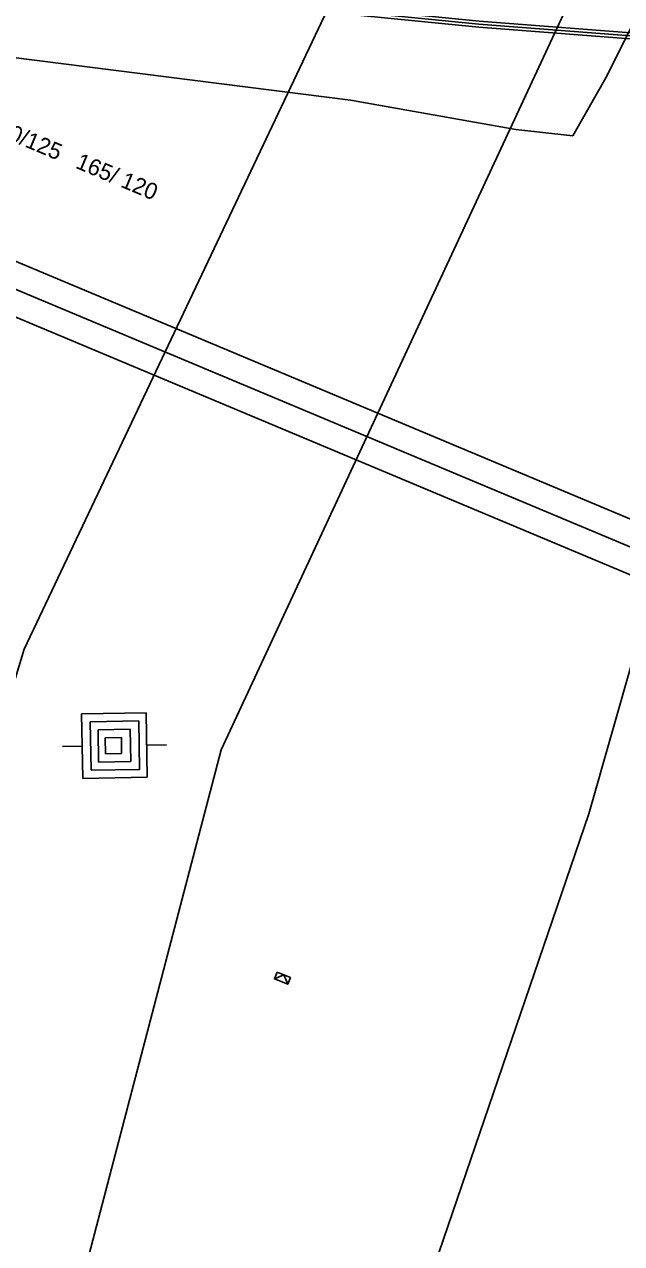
# Model space of a CAD drawing. Extents: x -596024 to -594475, y -1163820 to -1161957.
# Drawn here: x -594977.6 to -594948.5, y -1162194.5 to -1162135 of the extents above; entities that cross this region are included whole.
import ezdxf

# ---------------------------------------------------------------- set-up
doc = ezdxf.new("R2010")
doc.units = 0
for name, color, linetype in [('Vrstva 12', 7, 'Continuous'), ('Vrstva 19', 7, 'Continuous'), ('Vrstva 29', 7, 'Continuous'), ('Vrstva 30', 7, 'Continuous'), ('Vrstva 32', 7, 'Continuous'), ('Vrstva 42', 7, 'Continuous'), ('Vrstva 43', 7, 'Continuous'), ('Vrstva 47', 7, 'Continuous'), ('Vrstva 53', 7, 'Continuous')]:
    doc.layers.add(name, color=color, linetype=linetype)

# ---------------------------------------------------------------- blocks, each defined once
blk = doc.blocks.new('WN200')
at = {"layer": 'Vrstva 53'}
for points in [[(0, 6.3), (0, 10.136)], [(-6.299, 6.3), (6.299, 6.3)], [(-6.299, -6.3), (-6.299, 6.3)], [(6.299, 6.3), (6.299, -6.3)], [(-4.724, 4.625), (4.724, 4.625)], [(-4.724, -4.823), (-4.724, 4.625)], [(-3.149, 3.151), (3.149, 3.151)], [(-3.149, -3.151), (-3.149, 3.151)], [(3.149, 3.151), (3.149, -3.151)], [(4.724, 4.625), (4.724, -4.823)], [(-1.575, -1.378), (-1.575, 1.772)], [(-1.575, 1.772), (1.575, 1.772)], [(1.575, 1.772), (1.575, -1.378)], [(1.575, -1.378), (-1.575, -1.378)], [(3.149, -3.151), (-3.149, -3.151)], [(6.299, -6.3), (-6.299, -6.3)], [(4.724, -4.823), (-4.724, -4.823)], [(0, -6.3), (0, -10.136)]]:
    blk.add_lwpolyline(points, dxfattribs=at)

msp = doc.modelspace()

# ---------------------------------------------------------------- linework, layer by layer
at = {"layer": 'Vrstva 12'}
msp.add_lwpolyline([(-594938.65, -1162132.45), (-594939.94, -1162137.9), (-594940.48, -1162142.29), (-594945.83, -1162158.49), (-594946.79, -1162162.06), (-594950.07, -1162173.52), (-594957.82, -1162196.23), (-594973.83, -1162243.01), (-594986.34, -1162280.9), (-594995.28, -1162307.97), (-595001.11, -1162334.64), (-595000.94, -1162335.11), (-594999.28, -1162352.34), (-594997.66, -1162363.83), (-594996.8, -1162372.69), (-594994.36, -1162396.57), (-594993.55, -1162422.69), (-594989.89, -1162471.94), (-594989.27, -1162484.26), (-594988.21, -1162493.1)], dxfattribs=at)
at = {"layer": 'Vrstva 19'}
for points in [[(-595230.98, -1162092.97), (-595220.85, -1162096.4), (-595168.86, -1162107.75), (-595081.2, -1162125.02), (-594997.53, -1162134.17), (-594961.69, -1162138.72), (-594953.62, -1162140.15), (-594950.84, -1162140.46)], [(-594950.84, -1162140.46), (-594949.16, -1162137.51), (-594942.54, -1162124.16), (-594936.31, -1162112.2), (-594935.78, -1162111.19)]]:
    msp.add_lwpolyline(points, dxfattribs=at)
at = {"layer": 'Vrstva 29'}
msp.add_lwpolyline([(-594941.776, -1162163.139), (-594999.69, -1162138.853), (-595039.153, -1162134.53)], dxfattribs=at)
at = {"layer": 'Vrstva 30'}
for points in [[(-594942.214, -1162161.6), (-594999.374, -1162137.63), (-595040.011, -1162133.178)], [(-594941.337, -1162164.679), (-595000.006, -1162140.076), (-595038.295, -1162135.882)]]:
    msp.add_lwpolyline(points, dxfattribs=at)
at = {"layer": 'Vrstva 42'}
for points in [[(-595050.25, -1162124.49), (-595039.596, -1162125.409), (-595026.932, -1162127.038), (-595017.39, -1162128.669), (-595009.367, -1162129.499), (-594997.514, -1162130.979), (-594984.744, -1162131.839), (-594968.747, -1162133.829), (-594955.433, -1162135.149), (-594946.986, -1162135.809), (-594942.51, -1162136.43), (-594937.641, -1162136.39), (-594933.514, -1162135.941), (-594928.427, -1162136.761), (-594924.123, -1162136.5), (-594919.817, -1162136.951), (-594917.127, -1162136.548), (-594914.857, -1162136.19), (-594913.634, -1162136.17)], [(-594841.6, -1162165.96), (-594861.847, -1162157.553), (-594879.336, -1162150.176), (-594896.797, -1162142.418), (-594908.73, -1162137.65), (-594910.38, -1162137.12), (-594913.61, -1162136.02), (-594914.87, -1162136.04), (-594917.15, -1162136.4), (-594919.82, -1162136.8), (-594924.12, -1162136.35), (-594928.42, -1162136.61), (-594933.51, -1162135.79), (-594937.65, -1162136.24), (-594942.5, -1162136.28), (-594946.97, -1162135.66), (-594955.42, -1162135), (-594968.73, -1162133.68), (-594984.73, -1162131.69)], [(-594984.716, -1162131.541), (-594968.713, -1162133.531), (-594955.407, -1162134.851), (-594946.954, -1162135.511), (-594942.49, -1162136.13), (-594937.659, -1162136.09), (-594933.506, -1162135.639), (-594928.413, -1162136.459), (-594924.117, -1162136.2), (-594919.823, -1162136.649), (-594917.173, -1162136.252), (-594914.883, -1162135.89), (-594913.586, -1162135.87), (-594910.333, -1162136.978), (-594908.679, -1162137.509), (-594896.739, -1162142.28), (-594879.276, -1162150.038), (-594861.789, -1162157.415), (-594841.589, -1162165.801)]]:
    msp.add_lwpolyline(points, dxfattribs=at)
at = {"layer": 'Vrstva 43'}
for points in [[(-594964.613, -1162181.519), (-594964.744, -1162181.843), (-594965.394, -1162181.581), (-594965.262, -1162181.256)], [(-594964.613, -1162181.519), (-594965.262, -1162181.256)], [(-594964.938, -1162181.387), (-594965.394, -1162181.581)], [(-594964.938, -1162181.387), (-594964.744, -1162181.843)]]:
    msp.add_lwpolyline(points, dxfattribs=at)
at = {"layer": 'Vrstva 53'}
for points in [[(-594878.712, -1161956.88), (-594977.6, -1162165.5), (-594985.247, -1162190.772)], [(-594868.666, -1161956.88), (-594968, -1162170.4), (-594974.533, -1162195.382)]]:
    msp.add_lwpolyline(points, dxfattribs=at)

# ---------------------------------------------------------------- block references
at = {"layer": 'Vrstva 47', "xscale": 0.25, "yscale": 0.25, "rotation": 91}
msp.add_blockref('WN200', (-594973.2, -1162170.2), dxfattribs=at)

# ---------------------------------------------------------------- texts
at = {"layer": 'Vrstva 32'}
msp.add_text('DN 500/125   165/ 120', height=0.8, rotation=337.24296, dxfattribs=at).set_placement((-594981.23, -1162139.451))

doc.saveas('drawing.dxf')
